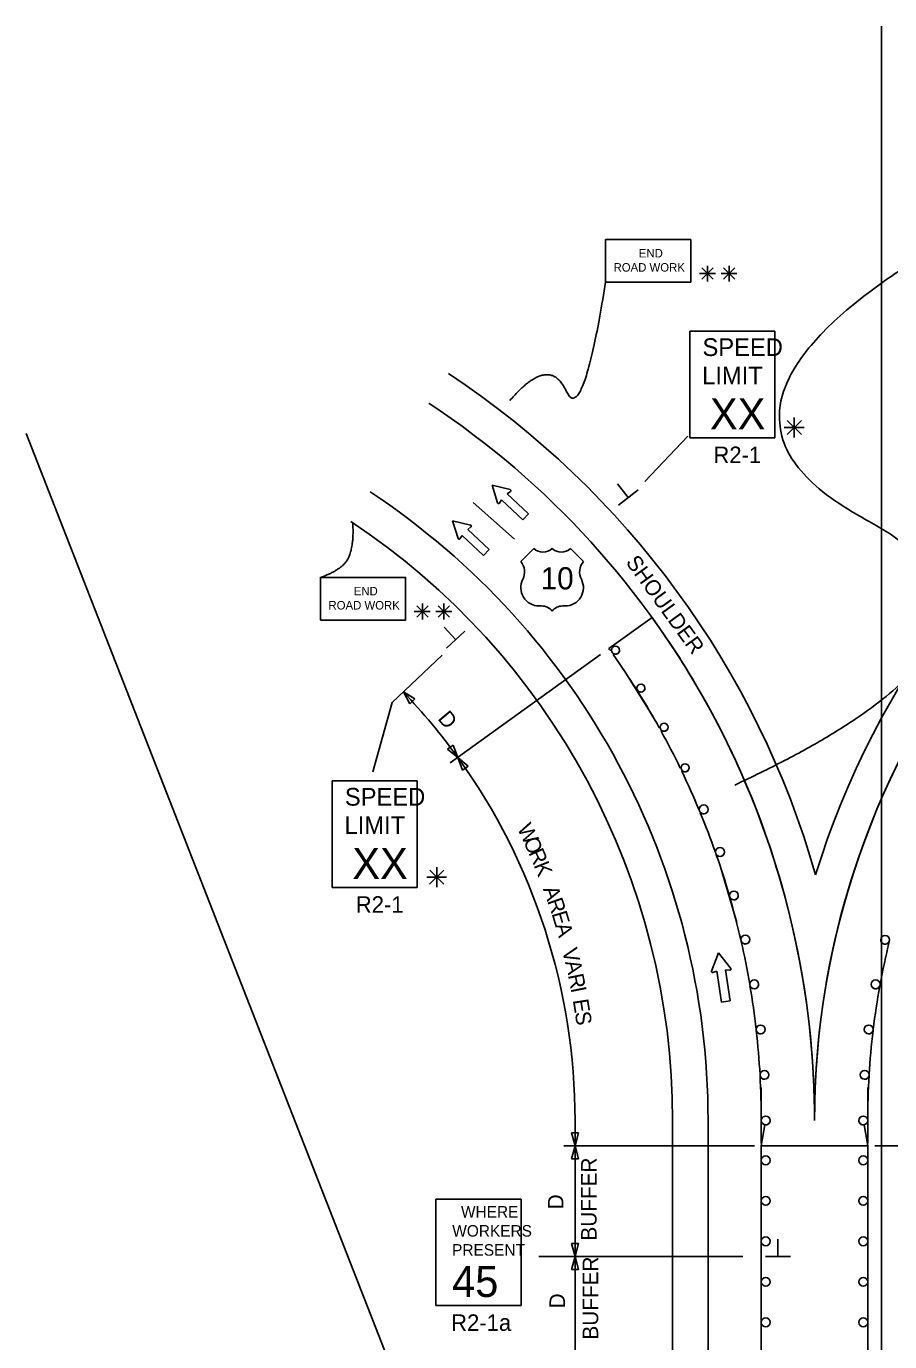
# Model space of a CAD drawing. Extents: x 16512 to 19504, y 5761 to 6984.
# Drawn here: x 16595 to 16984, y 6391 to 6984 of the extents above; entities that cross this region are included whole.
import ezdxf

# ---------------------------------------------------------------- set-up
doc = ezdxf.new("R2010")
doc.units = 0
for name, color, linetype in [('ALI_LEGAL_EX', 7, 'Continuous'), ('Level 3', 7, 'Continuous'), ('MT_SCRATCH_LEVEL_A', 7, 'Continuous'), ('MT_SCRATCH_LEVEL_E', 7, 'Continuous'), ('PAVT_EDGE_EX', 7, 'Continuous'), ('TRAFFIC_SIGNS_PR', 7, 'Continuous'), ('TYPICAL_EX', 7, 'Continuous'), ('TYPICAL_TEXT_DIMEN_PR', 7, 'Continuous')]:
    doc.layers.add(name, color=color, linetype=linetype)

msp = doc.modelspace()

# ---------------------------------------------------------------- linework, layer by layer
at = {"layer": 'ALI_LEGAL_EX'}
for p, q in [((16980.68, 6984.25), (16980.68, 6166.11)), ((16980.68, 6932.34), (16980.68, 6068.43)), ((16594.98, 6800.51), (16817, 6232.14))]:
    msp.add_line(p, q, dxfattribs=at)
for points in [[(16815.12, 6752.85), (16796.45, 6769.48)], [(16877.62, 6672.73), (16864.4, 6693.95)], [(16915.36, 6580.03), (16908.35, 6604.03)], [(16926.45, 6480.46), (16926.45, 6505.46)], [(16974.45, 6480.46), (16974.45, 6505.46)]]:
    msp.add_lwpolyline(points, dxfattribs=at)
at = {"layer": 'Level 3'}
for p, q in [((16842.45, 6429.22), (16842.45, 6479.22)), ((16842.45, 6379.15), (16842.45, 6429.22))]:
    msp.add_line(p, q, dxfattribs=at)
at = {"layer": 'MT_SCRATCH_LEVEL_A'}
for p, q in [((16926.45, 6479.22), (16974.45, 6479.22)), ((16974.45, 6479.22), (16926.45, 6479.22)), ((16974.24, 6479.22), (16974.45, 6479.43))]:
    msp.add_line(p, q, dxfattribs=at)
for points in [[(16877.19, 6717.56), (16857.72, 6703.52)], [(16858.22, 6702.83), (16858.9, 6702.83)], [(16860.1, 6701.1), (16859.67, 6700.8)], [(16869.94, 6685.45), (16870.34, 6685.71)], [(16871.36, 6684.09), (16870.96, 6683.84)], [(16880.44, 6667.8), (16880.81, 6668)], [(16881.65, 6666.48), (16881.28, 6666.28)], [(16889.92, 6649.57), (16890.27, 6649.74)], [(16890.94, 6648.34), (16890.6, 6648.17)], [(16898.34, 6630.91), (16898.49, 6630.98)], [(16899.07, 6629.57), (16898.92, 6629.51)], [(16905.72, 6611.72), (16905.83, 6611.76)], [(16906.27, 6610.52), (16906.16, 6610.48)], [(16912.01, 6592.15), (16912.09, 6592.17)], [(16912.4, 6591.11), (16912.32, 6591.09)], [(16917.19, 6572.24), (16917.24, 6572.26)], [(16917.44, 6571.39), (16917.38, 6571.38)], [(16984.13, 6571.22), (16984.07, 6571.23)], [(16984.29, 6572.15), (16984.35, 6572.14)], [(16921.23, 6552.08), (16921.26, 6552.08)], [(16921.37, 6551.43), (16921.34, 6551.42)], [(16979.9, 6551.33), (16979.87, 6551.34)], [(16979.99, 6552.04), (16980.03, 6552.03)], [(16924.12, 6531.72), (16924.14, 6531.72)], [(16924.19, 6531.27), (16924.17, 6531.27)], [(16976.88, 6531.23), (16976.86, 6531.23)], [(16976.91, 6531.7), (16976.93, 6531.7)], [(16925.87, 6511.22), (16925.87, 6511.22)], [(16925.88, 6511), (16925.88, 6511)], [(16975.05, 6510.98), (16975.05, 6510.98)], [(16975.06, 6511.22), (16975.07, 6511.22)], [(16926.45, 6490.66), (16926.45, 6490.66)], [(16928.11, 6488.69), (16926.45, 6479.22), (16974.45, 6479.22), (16972.78, 6488.69)], [(16974.44, 6490.66), (16974.45, 6490.66)]]:
    msp.add_lwpolyline(points, dxfattribs=at)
for centre, radius, start, end in [((16562.45, 6490.66), 388, 22.85544, 35.78734), ((17314.45, 6490.66), 364, 141.75977, 180), ((16562.45, 6490.66), 364, 35.6537, 35.78734), ((16860.7, 6702.8), 1.8, 0, 179.09783), ((16562.45, 6490.66), 364, 32.35359, 35.26027), ((16860.7, 6702.8), 1.8, 250.52055, 0), ((16872.14, 6685.71), 1.8, 0, 180), ((16562.45, 6490.66), 364, 29.11978, 32.05325), ((16872.14, 6685.71), 1.8, 244.1065, 0), ((16882.61, 6668.01), 1.8, 0, 180), ((16562.45, 6490.66), 364, 25.88552, 28.8467), ((16882.61, 6668.01), 1.8, 237.69339, 0), ((16892.07, 6649.74), 1.8, 0, 180), ((16562.45, 6490.66), 364, 22.66299, 25.64057), ((16892.07, 6649.74), 1.8, 231.28113, 0), ((16562.45, 6490.66), 388, 0, 22.85544), ((16900.49, 6630.98), 2, 0, 180), ((16562.45, 6490.66), 364, 19.42615, 22.42293), ((16900.49, 6630.98), 2, 224.84586, 0), ((16907.83, 6611.76), 2, 0, 180), ((16562.45, 6490.66), 364, 16.18897, 19.21895), ((16907.83, 6611.76), 2, 218.43791, 0), ((16914.09, 6592.17), 2, 0, 180), ((16562.45, 6490.66), 364, 12.95151, 16.0153), ((16914.09, 6592.17), 2, 212.0306, 0), ((16919.24, 6572.26), 2, 0, 180), ((16562.45, 6490.66), 364, 9.71384, 12.81192), ((16919.24, 6572.26), 2, 205.62383, 0), ((17314.45, 6490.66), 340, 166.29418, 169.60061), ((16982.29, 6572.16), 2, 0, 180), ((16982.29, 6572.16), 2, 180, 332.58835), ((16923.26, 6552.08), 2, 0, 180), ((16562.45, 6490.66), 364, 6.47598, 9.60875), ((16923.26, 6552.08), 2, 199.2175, 0), ((16978, 6552.04), 2, 0, 180), ((16978, 6552.04), 2, 180, 339.44176), ((17314.45, 6490.66), 340, 169.72088, 173.06695), ((16926.14, 6531.72), 2, 0, 180), ((16974.91, 6531.71), 2, 0, 180), ((16562.45, 6490.66), 364, 3.23802, 6.40574), ((16926.14, 6531.72), 2, 192.81148, 0), ((16974.91, 6531.71), 2, 180, 346.29474), ((17314.45, 6490.66), 340, 173.14737, 176.53344), ((16927.87, 6511.22), 2, 0, 180), ((16927.87, 6511.22), 2, 186.40569, 0), ((16562.45, 6490.66), 364, 0, 3.20284), ((16973.06, 6511.22), 2, 0, 180), ((16973.06, 6511.22), 2, 180, 353.14744), ((17314.45, 6490.66), 340, 176.57372, 180), ((16928.45, 6490.66), 2, 0, 180), ((16972.44, 6490.66), 2, 0, 180), ((16928.45, 6490.66), 2, 260.0595, 0), ((16972.44, 6490.66), 2, 180, 279.941)]:
    msp.add_arc(centre, radius, start, end, dxfattribs=at)
at = {"layer": 'MT_SCRATCH_LEVEL_E'}
for p, q in [((16813.17, 6775.28), (16805.06, 6777.25)), ((16805.06, 6777.25), (16807.49, 6769.28)), ((16808.32, 6769.16), (16809.31, 6770.67)), ((16809.31, 6770.67), (16818.94, 6761.55)), ((16811.89, 6773.38), (16813.34, 6774.46)), ((16821.51, 6764.27), (16811.89, 6773.38)), ((16795.35, 6759.2), (16787.24, 6761.17)), ((16787.24, 6761.17), (16789.67, 6753.2)), ((16818.94, 6761.55), (16821.51, 6764.27)), ((16790.5, 6753.08), (16791.5, 6754.59)), ((16791.5, 6754.59), (16801.12, 6745.47)), ((16794.07, 6757.31), (16795.52, 6758.38)), ((16803.69, 6748.19), (16794.07, 6757.31)), ((16801.12, 6745.47), (16803.69, 6748.19))]:
    msp.add_line(p, q, dxfattribs=at)
for centre, start, end in [((16813.05, 6774.83), 306.59404, 76.33096), ((16807.94, 6769.42), 196.98269, 326.52165), ((16795.23, 6758.75), 306.59404, 76.33096), ((16790.12, 6753.34), 196.98269, 326.52165)]:
    msp.add_arc(centre, 0.463, start, end, dxfattribs=at)
at = {"layer": 'PAVT_EDGE_EX'}
for p, q in [((16886.45, 6490.66), (16886.45, 6058.52)), ((16902.45, 6490.66), (16902.45, 6058.52))]:
    msp.add_line(p, q, dxfattribs=at)
msp.add_lwpolyline([(16974.45, 6479.22), (16926.45, 6479.22), (16926.45, 6379.15), (16974.45, 6379.15)], close=True, dxfattribs=at)
for centre, radius, start, end in [((16562.45, 6490.66), 404, 15.917, 56.50367), ((16562.45, 6490.66), 388, 0, 56.50367), ((17314.45, 6490.66), 380, 121.93275, 163.04831), ((17314.45, 6490.66), 364, 121.93275, 180), ((16562.45, 6490.66), 340, 0, 56.50367), ((16562.45, 6490.66), 324, 0, 56.50367)]:
    msp.add_arc(centre, radius, start, end, dxfattribs=at)
at = {"layer": 'TRAFFIC_SIGNS_PR'}
for p, q in [((16894.17, 6846.66), (16932.57, 6846.66)), ((16894.17, 6798.66), (16894.17, 6846.66)), ((16932.57, 6798.66), (16932.57, 6846.66)), ((16894.17, 6798.66), (16932.57, 6798.66)), ((16732.88, 6643.81), (16771.28, 6643.81)), ((16732.88, 6595.81), (16732.88, 6643.81)), ((16771.28, 6595.81), (16771.28, 6643.81)), ((16732.88, 6595.81), (16771.28, 6595.81)), ((16779.7, 6455.18), (16818.1, 6455.18)), ((16779.7, 6407.18), (16779.7, 6455.18)), ((16818.1, 6407.18), (16818.1, 6455.18)), ((16779.7, 6407.18), (16818.1, 6407.18))]:
    msp.add_line(p, q, dxfattribs=at)
for points in [[(16856.22, 6868.85), (16894.62, 6868.85), (16894.62, 6888.05), (16856.22, 6888.05)], [(16727.65, 6716.42), (16766.05, 6716.42), (16766.05, 6735.62), (16727.65, 6735.62)]]:
    msp.add_lwpolyline(points, close=True, dxfattribs=at)
for centre, radius in [((16860.7, 6702.8), 1.8), ((16872.14, 6685.71), 1.8), ((16882.61, 6668.01), 1.8), ((16892.07, 6649.74), 1.8), ((16900.49, 6630.98), 2), ((16907.83, 6611.76), 2), ((16914.09, 6592.17), 2), ((16919.24, 6572.26), 2), ((16982.29, 6572.16), 2), ((16923.26, 6552.08), 2), ((16978, 6552.04), 2), ((16926.14, 6531.72), 2), ((16974.91, 6531.71), 2), ((16927.87, 6511.22), 2), ((16973.06, 6511.22), 2), ((16928.45, 6490.66), 2), ((16972.44, 6490.66), 2), ((16928.45, 6472.66), 2), ((16972.44, 6472.66), 2), ((16928.45, 6454.4), 2), ((16972.44, 6454.4), 2), ((16928.45, 6436.13), 2), ((16972.44, 6436.13), 2), ((16928.45, 6417.87), 2), ((16972.44, 6417.87), 2), ((16928.45, 6399.6), 2), ((16972.44, 6399.6), 2)]:
    msp.add_circle(centre, radius, dxfattribs=at)
at = {"layer": 'TYPICAL_EX'}
for p, q in [((16817.96, 6742.82), (16823.85, 6748.71)), ((16846.26, 6742.82), (16840.36, 6748.71)), ((16826.2, 6722.76), (16827.38, 6722.76)), ((16838.01, 6722.76), (16836.83, 6722.76))]:
    msp.add_line(p, q, dxfattribs=at)
for centre, radius, start, end in [((16827.98, 6753.01), 5.96, 226.14041, 313.85958), ((16836.23, 6753.01), 5.96, 226.14042, 313.85959), ((16812.37, 6738.1), 7.31, 333.09768, 40.19361), ((16851.84, 6738.1), 7.31, 139.80639, 206.90233), ((16826.22, 6731), 8.24, 152.6698, 269.90132), ((16837.99, 6731), 8.24, 270.09868, 27.3302), ((16827.4, 6716.85), 5.91, 37.1038, 90.13853), ((16836.82, 6716.85), 5.91, 89.86147, 142.8962)]:
    msp.add_arc(centre, radius, start, end, dxfattribs=at)
at = {"layer": 'TYPICAL_TEXT_DIMEN_PR'}
for p, q in [((16902.17, 6872.67), (16898.54, 6872.67)), ((16904.72, 6875.22), (16899.61, 6870.12)), ((16899.62, 6875.22), (16904.72, 6870.12)), ((16902.17, 6872.67), (16902.17, 6876.23)), ((16902.17, 6872.67), (16904.72, 6872.67)), ((16902.17, 6872.67), (16905.75, 6872.67)), ((16902.17, 6872.67), (16902.17, 6869.07)), ((16911.91, 6872.67), (16908.28, 6872.67)), ((16909.36, 6875.22), (16914.46, 6870.12)), ((16914.46, 6875.22), (16909.36, 6870.12)), ((16911.91, 6872.67), (16911.91, 6876.23)), ((16911.91, 6872.67), (16914.46, 6872.67)), ((16911.91, 6872.67), (16915.49, 6872.67)), ((16911.91, 6872.67), (16911.91, 6869.07)), ((16944.54, 6806.46), (16938.16, 6800.08)), ((16938.17, 6806.46), (16944.54, 6800.08)), ((16941.35, 6803.27), (16941.35, 6807.73)), ((16941.35, 6803.27), (16936.82, 6803.27)), ((16941.35, 6803.27), (16944.54, 6803.27)), ((16941.35, 6803.27), (16945.83, 6803.27)), ((16941.35, 6803.27), (16941.35, 6798.77)), ((16893.38, 6799.41), (16873.98, 6778.98)), ((16866.48, 6771.71), (16861.61, 6777.78)), ((16870.87, 6775.22), (16862.09, 6768.19)), ((16773.6, 6720.24), (16773.6, 6723.81)), ((16783.34, 6720.24), (16783.34, 6723.81)), ((16773.6, 6720.24), (16769.97, 6720.24)), ((16771.05, 6722.79), (16776.15, 6717.69)), ((16776.15, 6722.79), (16771.05, 6717.69)), ((16773.6, 6720.24), (16776.15, 6720.24)), ((16773.6, 6720.24), (16777.18, 6720.24)), ((16773.6, 6720.24), (16773.6, 6716.64)), ((16783.34, 6720.24), (16779.72, 6720.24)), ((16780.79, 6722.79), (16785.89, 6717.69)), ((16785.89, 6722.79), (16780.79, 6717.69)), ((16783.34, 6720.24), (16785.89, 6720.24)), ((16783.34, 6720.24), (16786.92, 6720.24)), ((16783.34, 6720.24), (16783.34, 6716.64)), ((16788.67, 6707.54), (16783.39, 6713.26)), ((16792.81, 6711.36), (16784.54, 6703.72)), ((16782.47, 6700.61), (16759.98, 6679.15)), ((16853.94, 6700.79), (16786.14, 6651.92)), ((16767.93, 6678.63), (16765.02, 6683.96)), ((16765.02, 6683.96), (16770.2, 6680.8)), ((16751.28, 6647.97), (16759.98, 6679.15)), ((16769.07, 6679.72), (16767.93, 6678.63)), ((16770.2, 6680.8), (16769.07, 6679.72)), ((16784.92, 6658.18), (16786.2, 6659.09)), ((16789.62, 6654.34), (16784.92, 6658.18)), ((16786.2, 6659.09), (16787.47, 6660.01)), ((16787.47, 6660.01), (16789.62, 6654.34)), ((16791.72, 6648.71), (16789.56, 6654.39)), ((16789.56, 6654.39), (16794.27, 6650.55)), ((16792.99, 6649.63), (16791.72, 6648.71)), ((16794.27, 6650.55), (16792.99, 6649.63)), ((16780.07, 6600.42), (16780.07, 6604.88)), ((16780.07, 6600.42), (16775.54, 6600.42)), ((16783.26, 6603.61), (16776.88, 6597.24)), ((16776.89, 6603.61), (16783.26, 6597.24)), ((16780.07, 6600.42), (16783.26, 6600.42)), ((16780.07, 6600.42), (16784.55, 6600.42)), ((16780.07, 6600.42), (16780.07, 6595.92)), ((16907.2, 6566.28), (16903.97, 6558.01)), ((16912.69, 6559.28), (16907.2, 6566.28)), ((16904.59, 6557.36), (16906.41, 6557.96)), ((16906.41, 6557.96), (16908.45, 6543.97)), ((16912.4, 6544.55), (16910.36, 6558.54)), ((16910.36, 6558.54), (16912.29, 6558.48)), ((16908.45, 6543.97), (16912.4, 6544.55)), ((16842.45, 6490.66), (16842.45, 6479.22)), ((16842.45, 6490.66), (16842.45, 6479.22)), ((16842.45, 6479.22), (16840.88, 6485.08)), ((16840.88, 6485.08), (16842.45, 6485.08)), ((16842.45, 6485.08), (16844.02, 6485.08)), ((16844.02, 6485.08), (16842.45, 6479.22)), ((16923.32, 6479.22), (16837.45, 6479.22)), ((16840.88, 6473.35), (16842.45, 6479.22)), ((16842.45, 6479.22), (16844.02, 6473.35)), ((16977.64, 6479.22), (17063.45, 6479.22)), ((16842.45, 6473.35), (16840.88, 6473.35)), ((16844.02, 6473.35), (16842.45, 6473.35)), ((16842.45, 6429.22), (16840.88, 6435.08)), ((16840.88, 6435.08), (16842.45, 6435.08)), ((16842.45, 6435.08), (16844.02, 6435.08)), ((16844.02, 6435.08), (16842.45, 6429.22)), ((16933.95, 6429.34), (16933.95, 6437.12)), ((16826.13, 6429.22), (16918.11, 6429.22)), ((16840.88, 6423.35), (16842.45, 6429.22)), ((16842.45, 6429.22), (16844.02, 6423.35)), ((16939.57, 6429.34), (16928.32, 6429.34)), ((16842.45, 6423.35), (16840.88, 6423.35)), ((16844.02, 6423.35), (16842.45, 6423.35))]:
    msp.add_line(p, q, dxfattribs=at)
for centre, radius, start, end in [((16562.45, 6490.66), 280, 35.77202, 43.65759), ((16562.45, 6490.66), 280, 0, 35.77202), ((16904.44, 6557.83), 0.494, 158.71004, 288.24901), ((16912.29, 6558.98), 0.494, 268.32139, 38.05832)]:
    msp.add_arc(centre, radius, start, end, dxfattribs=at)
for points in [[(16914.57, 6641.97), (17065.5, 6712.4), (16880.62, 6811.77), (17010.16, 6887.23)], [(16813.09, 6815.48), (16830.93, 6836.26), (16845.88, 6803.39), (16856.22, 6868.85)], [(16742.2, 6759.91), (16742.81, 6750.52), (16738.12, 6739.3), (16727.65, 6735.62)]]:
    msp.add_open_spline(points, degree=2, dxfattribs=at)

# ---------------------------------------------------------------- texts
at = {"layer": 'TRAFFIC_SIGNS_PR'}
for s, height, p in [('END', 3.831, (16871.22, 6879.98)), ('ROAD WORK', 3.831, (16859.83, 6873.59)), ('SPEED', 8, (16899.93, 6835.52)), ('LIMIT', 8, (16899.77, 6822.72)), ('XX', 14.031, (16903.28, 6802.42)), ('R2-1', 7.44, (16904.84, 6787.22)), ('END', 3.831, (16742.65, 6727.55)), ('ROAD WORK', 3.831, (16731.26, 6721.16)), ('SPEED', 8, (16738.65, 6632.67)), ('LIMIT', 8, (16738.49, 6619.87)), ('XX', 14.031, (16742, 6599.57)), ('R2-1', 7.44, (16743.56, 6584.37)), ('WHERE', 5.2, (16791.01, 6446.86)), ('WORKERS', 5.2, (16787.08, 6438.26)), ('PRESENT', 5.2, (16787.01, 6429.66)), ('45', 14.031, (16787, 6411.03)), ('R2-1a', 7.44, (16786.55, 6395.74))]:
    msp.add_text(s, height=height, dxfattribs=at).set_placement(p)
at = {"layer": 'TYPICAL_EX'}
msp.add_text('10', height=10, dxfattribs=at).set_placement((16826.95, 6730.24))
at = {"layer": 'TYPICAL_TEXT_DIMEN_PR'}
for s, rotation, p in [('SHOULDER', 305.94893, (16865.05, 6742.42)), ('D', 310, (16780.2, 6671.82)), ('W', 296.90518, (16816.15, 6622.47)), ('O', 294.34279, (16818.92, 6616.69)), ('R', 294.34279, (16821.29, 6611.43)), ('K', 291.78039, (16823.71, 6605.82)), ('A', 289.21799, (16827.93, 6595.11)), ('R', 289.21799, (16829.82, 6589.67)), ('E', 286.65559, (16831.79, 6584.01)), ('A', 286.65559, (16833.38, 6578.69)), ('V', 284.09319, (16836.52, 6567.5)), ('A', 284.09319, (16837.88, 6562.1)), ('R', 281.53079, (16839.21, 6556.18)), ('I', 281.53079, (16840.42, 6550.28)), ('E', 278.96839, (16841.42, 6544.94)), ('S', 278.96839, (16842.3, 6539.35)), ('BUFFER', 89.97949, (16852.18, 6436.48)), ('D', 89.88679, (16837.21, 6450.55)), ('BUFFER', 89.97949, (16852.89, 6391.81)), ('D', 89.88679, (16837.91, 6405.87))]:
    msp.add_text(s, height=7, rotation=rotation, dxfattribs=at).set_placement(p)

doc.saveas('drawing.dxf')
